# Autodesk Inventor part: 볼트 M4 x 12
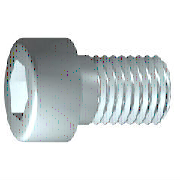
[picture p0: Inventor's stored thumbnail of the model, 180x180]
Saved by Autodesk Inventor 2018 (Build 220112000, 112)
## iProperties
IsCustomPart: 0
Created: 2012-02
Part Number: 볼트 M4 x 12
Material: 강철, 연강
Description: 6각 소켓 머리 캡 나사
Document SubType Name: Modeling
Standard: ISO 4762
Designer: mduedu
Standard Revision: Fourth edition 2004-03-01
Standards Organization: ISO
Language: ko-KR
Size Designation: M4 x 12
Categories: <MemberInstance><Categories><Category DisplayName="조임쇠" InternalName="e4da775c-781d-43d5-af7c-5136215cf5a6" Mnemonic="FSTN"><Category DisplayName="볼트" InternalN
Density: 7.86 g/cm^3
Mass: 2.23465 g
Surface Area: 3.30853 cm^2
Volume: 0.284306 cm^3
Appearance: 강철
Author: mduedu
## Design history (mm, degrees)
sketch "스케치1"
  geometry: L1 (-1, 0)-(12, 0); L2 (12, 0)-(12, 2); L3 (12, 2)-(1.75, 2); L4 (1.75, 2)-(1.32, 2); L5 (1.32, 2)-(0, 2); L6 (0, 2)-(0, 3.5); L7 (0, 3.5)-(-4, 3.5); L8 (-4, 3.5)-(-4, 1.732); L9 (-4, 1.732)-(-2, 1.732); L10 (-2, 1.732)-(-1, 0); L11 (-7.2, 0)-(15.2, 0) reference; L12 (0, -0.7)-(0, 4.2) reference; L13 (1.75, 2)-(0, 2)
  constraints: 22 end point, 6 parallel, 2 collinear, 2 perpendicular, 1 horizontal, 1 point on line
  dimensions: "d1" = 10.25 distance from line of L3.end L2 (= GEL); "d2" = 0.42952 distance of L4.end L3.end (computed from GAL); "d3" = 4 distance between parallel lines of L8 L6 (= KOH); "d4" = 2 distance of L8.end L9.end (= INTI); "d5" = 60 deg angle of L10 L1; "d6" = 4 diameter of L3 L1 (= GD); "d7" = 4 diameter of L5 L1 (= BDM); "d8" = 3.4641 diameter of L9 L1 (= 1.1547 x SW); "d9" = 7 diameter of L7 L1 (= KOD); "d26" = 12 distance between parallel lines of L12 L2 (= NLG)
revolve "본체" sketch "스케치1" stored, may be unused: angle "d10" = 90 deg
sketch "스케치2"
  geometry: L1 (0, -4.9)-(0, 4.9) reference; L2 (-4.9, 0)-(4.9, 0) reference; L3 (1.732, 0)-(0.866, -1.5); L4 (0.866, -1.5)-(-0.866, -1.5); L5 (-0.866, -1.5)-(-1.732, 0); L6 (-1.732, 0)-(-0.866, 1.5); L7 (-0.866, 1.5)-(0.866, 1.5); L8 (0.866, 1.5)-(1.732, 0); 2 further points
  constraints: 12 end point, 1 coincident, 1 horizontal alignment, 1 point on line, 12 other
extrude "슬롯" join sketch "스케치2" stored distance "d11" = 10; taper "d12" = 0 deg
workplane "Work Plane1"
fillet "Fillet2" dims "d30" = 0.1 (= R)
body "Solid1"
fillet "모깎기1" dims "d17" = 0.4 (= RR)
feature "스레드" dims "d13" = 10.25 (= GEL), "d14" = 0
chamfer "모따기1" distance "d15" = 0.42941 (= -0.5 x SPD + 0.5 x GD); stored, may be unused: second distance "d16" = 0.42941 (= GUL), angle "d27" = 45 deg
other parameters: "GD" = 4 [user parameter; used in 2 equation terms], "NLG" = 12 [user parameter; used in 1 equation term], "GEL" = 10.25 [user parameter; used in 2 equation terms], "KOD" = 7 [user parameter; used in 1 equation term], "KOH" = 4 [user parameter; used in 1 equation term], "INTI" = 2 [user parameter; used in 1 equation term], "GAL" = 0.42941 (= 0.61345 x PTC) [user parameter; used in 1 equation term], "GUL" = 0.42941 (= 0.61345 x PTC) [user parameter; used in 1 equation term], "BDM" = 4 (= NND) [user parameter; used in 1 equation term], "SW" = 3 [user parameter; used in 2 equation terms], "RR" = 0.4 [user parameter; used in 1 equation term], "SPD" = 3.14117 (= NND - 1.2269 x PTC) [user parameter; used in 1 equation term], "d19" = 0, "d28" = 0, "d29" = 0, "R" = 0.1 [user parameter; used in 1 equation term], "TOA" = 30 deg [user parameter], "GD1" = 3.14117 (= THREADDIA - 1.2269 x PTC) [user parameter], "THREADDIA" = 4 [user parameter; used in 1 equation term], "FAWI" = 45 deg [user parameter], "TPU" = 14.28571 (computed from PTC) [user parameter], "PTC" = 0.7 [user parameter; used in 5 equation terms], "NND" = 4 [user parameter; used in 2 equation terms], "E0" = 3.465 (= 1.155 x SW) [user parameter]
